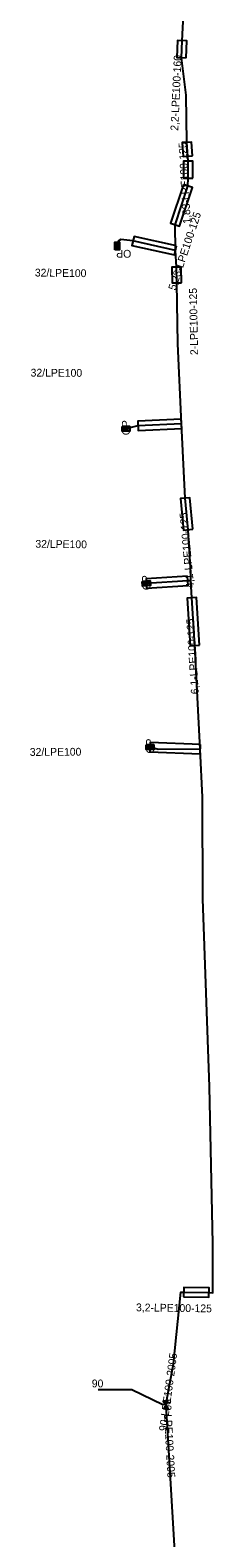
# Model space of a CAD drawing. Extents: x -762921 to -762499, y -1152946 to -1152170.
# Drawn here: x -762777.9 to -762754.4, y -1152560 to -1152366.3 of the extents above; entities that cross this region are included whole.
import ezdxf

# ---------------------------------------------------------------- set-up
doc = ezdxf.new("R2010")
doc.units = 0
for name, color, linetype in [('Vrstva 21', 7, 'Continuous'), ('Vrstva 22', 7, 'Continuous'), ('Vrstva 29', 7, 'Continuous'), ('Vrstva 31', 7, 'Continuous'), ('Vrstva 32', 7, 'Continuous')]:
    doc.layers.add(name, color=color, linetype=linetype)

msp = doc.modelspace()

# ---------------------------------------------------------------- linework, layer by layer
at = {"layer": 'Vrstva 21'}
for points in [[(-762760.45, -1152542.92), (-762759.48, -1152537.62), (-762758.55, -1152528.42), (-762758.16, -1152528.42), (-762754.92, -1152528.47), (-762754.43, -1152528.5), (-762754.43, -1152522.18), (-762754.86, -1152502.03), (-762755.69, -1152477.87), (-762755.75, -1152464.8), (-762756.04, -1152458.65), (-762756.74, -1152445.33), (-762757.13, -1152439.2), (-762757.27, -1152437), (-762757.25, -1152435.97), (-762757.61, -1152430.45), (-762757.98, -1152426.4), (-762758.45, -1152416.83), (-762758.91, -1152406.58), (-762759.05, -1152398.74), (-762759.09, -1152396.71), (-762759.23, -1152394.56), (-762759.27, -1152391.26), (-762757.62, -1152386.29), (-762757.61, -1152385.28), (-762757.61, -1152383.09), (-762757.65, -1152382.46), (-762757.75, -1152380.67), (-762757.84, -1152374.62), (-762758.45, -1152369.81), (-762758.35, -1152367.62), (-762758.14, -1152363.48)], [(-762760.45, -1152542.92), (-762757.89, -1152586.28)]]:
    msp.add_lwpolyline(points, dxfattribs=at)
at = {"layer": 'Vrstva 22'}
for points in [[(-762769.15, -1152540.9), (-762764.8, -1152540.9), (-762760.85, -1152542.85)], [(-762760.72, -1152543.437), (-762760.18, -1152542.404), (-762760.779, -1152542.439), (-762760.121, -1152543.402), (-762760.72, -1152543.437)]]:
    msp.add_lwpolyline(points, dxfattribs=at)
at = {"layer": 'Vrstva 29'}
for points in [[(-762757.85, -1152369.84), (-762757.75, -1152367.65), (-762758.95, -1152367.59), (-762759.05, -1152369.78)], [(-762757.05, -1152382.43), (-762757.15, -1152380.64), (-762758.35, -1152380.7), (-762758.25, -1152382.49)], [(-762757.01, -1152385.28), (-762757.01, -1152383.09), (-762758.21, -1152383.09), (-762758.21, -1152385.28)], [(-762758.19, -1152386.1), (-762759.84, -1152391.07), (-762758.7, -1152391.45), (-762757.05, -1152386.48)], [(-762759.1, -1152393.97), (-762764.54, -1152392.76), (-762764.8, -1152393.94), (-762759.36, -1152395.15)], [(-762758.45, -1152398.73), (-762758.49, -1152396.7), (-762759.69, -1152396.72), (-762759.65, -1152398.75)], [(-762758.48, -1152416.23), (-762764.07, -1152416.51), (-762764.01, -1152417.71), (-762758.42, -1152417.43)], [(-762757.01, -1152430.4), (-762757.38, -1152426.35), (-762758.58, -1152426.45), (-762758.21, -1152430.5)], [(-762757.66, -1152436.4), (-762763, -1152436.75), (-762762.92, -1152437.95), (-762757.58, -1152437.6)], [(-762756.14, -1152445.29), (-762756.53, -1152439.16), (-762757.73, -1152439.24), (-762757.34, -1152445.37)], [(-762756.02, -1152458.05), (-762762.46, -1152457.79), (-762762.5, -1152458.99), (-762756.06, -1152459.25)], [(-762758.17, -1152529.02), (-762754.93, -1152529.07), (-762754.91, -1152527.87), (-762758.15, -1152527.82)]]:
    msp.add_lwpolyline(points, close=True, dxfattribs=at)
at = {"layer": 'Vrstva 31'}
for points in [[(-762759.23, -1152394.56), (-762764.67, -1152393.35), (-762766.25, -1152393.18), (-762766.58, -1152393.39), (-762766.69, -1152394)], [(-762758.45, -1152416.83), (-762764.04, -1152417.11), (-762765.57, -1152417.48)], [(-762757.27, -1152437), (-762757.62, -1152437), (-762762.96, -1152437.35)], [(-762756.04, -1152458.65), (-762761.46, -1152458.68), (-762762.48, -1152458.39)]]:
    msp.add_lwpolyline(points, dxfattribs=at)
at = {"layer": 'Vrstva 32'}
for p, q in [((-762766.516, -1152394.2), (-762766.866, -1152394.198)), ((-762766.514, -1152393.801), (-762766.864, -1152393.799)), ((-762766.702, -1152394.4), (-762766.701, -1152394.199)), ((-762766.867, -1152394.399), (-762766.517, -1152394.401)), ((-762765.975, -1152417.315), (-762765.966, -1152417.665)), ((-762765.97, -1152417.48), (-762765.769, -1152417.475)), ((-762765.765, -1152417.66), (-762765.774, -1152417.31)), ((-762765.366, -1152417.65), (-762765.375, -1152417.3)), ((-762763.37, -1152437.202), (-762763.347, -1152437.551)), ((-762763.359, -1152437.367), (-762763.159, -1152437.353)), ((-762763.147, -1152437.538), (-762763.17, -1152437.189)), ((-762762.749, -1152437.512), (-762762.772, -1152437.163)), ((-762762.884, -1152458.224), (-762762.876, -1152458.574)), ((-762762.88, -1152458.389), (-762762.679, -1152458.384)), ((-762762.675, -1152458.569), (-762762.683, -1152458.219)), ((-762762.276, -1152458.56), (-762762.284, -1152458.21))]:
    msp.add_line(p, q, dxfattribs=at)
for points in [[(-762766.993, -1152394.498), (-762766.987, -1152393.498), (-762766.387, -1152393.502), (-762766.393, -1152394.502), (-762766.993, -1152394.498)], [(-762766.865, -1152394.099), (-762766.614, -1152394.101), (-762766.565, -1152394.087), (-762766.532, -1152394.056), (-762766.515, -1152394.014), (-762766.515, -1152393.985), (-762766.531, -1152393.943), (-762766.564, -1152393.914), (-762766.613, -1152393.9), (-762766.864, -1152393.898)], [(-762766.864, -1152393.799), (-762766.863, -1152393.669), (-762766.845, -1152393.627), (-762766.829, -1152393.612), (-762766.796, -1152393.598), (-762766.746, -1152393.599), (-762766.713, -1152393.613), (-762766.697, -1152393.628), (-762766.681, -1152393.67), (-762766.682, -1152393.8)], [(-762766.078, -1152417.193), (-762765.078, -1152417.167), (-762765.063, -1152417.767), (-762766.062, -1152417.792), (-762766.078, -1152417.193)], [(-762765.675, -1152417.307), (-762765.668, -1152417.558), (-762765.653, -1152417.607), (-762765.621, -1152417.639), (-762765.579, -1152417.655), (-762765.55, -1152417.654), (-762765.508, -1152417.636), (-762765.48, -1152417.602), (-762765.467, -1152417.553), (-762765.474, -1152417.302)], [(-762765.375, -1152417.3), (-762765.245, -1152417.296), (-762765.202, -1152417.312), (-762765.187, -1152417.328), (-762765.172, -1152417.36), (-762765.171, -1152417.41), (-762765.184, -1152417.444), (-762765.199, -1152417.46), (-762765.24, -1152417.478), (-762765.37, -1152417.482)], [(-762763.478, -1152437.084), (-762762.48, -1152437.018), (-762762.441, -1152437.617), (-762763.439, -1152437.682), (-762763.478, -1152437.084)], [(-762763.071, -1152437.182), (-762763.055, -1152437.433), (-762763.037, -1152437.481), (-762763.004, -1152437.512), (-762762.961, -1152437.526), (-762762.932, -1152437.524), (-762762.891, -1152437.504), (-762762.865, -1152437.469), (-762762.854, -1152437.42), (-762762.87, -1152437.169)], [(-762762.772, -1152437.163), (-762762.642, -1152437.154), (-762762.599, -1152437.168), (-762762.583, -1152437.183), (-762762.567, -1152437.215), (-762762.563, -1152437.265), (-762762.575, -1152437.299), (-762762.589, -1152437.316), (-762762.63, -1152437.336), (-762762.76, -1152437.344)], [(-762762.987, -1152458.101), (-762761.987, -1152458.078), (-762761.973, -1152458.678), (-762762.973, -1152458.701), (-762762.987, -1152458.101)], [(-762762.584, -1152458.217), (-762762.578, -1152458.468), (-762762.563, -1152458.516), (-762762.531, -1152458.549), (-762762.489, -1152458.565), (-762762.46, -1152458.564), (-762762.418, -1152458.546), (-762762.39, -1152458.512), (-762762.377, -1152458.463), (-762762.383, -1152458.212)], [(-762762.284, -1152458.21), (-762762.154, -1152458.207), (-762762.112, -1152458.223), (-762762.096, -1152458.239), (-762762.082, -1152458.271), (-762762.08, -1152458.321), (-762762.094, -1152458.355), (-762762.108, -1152458.371), (-762762.15, -1152458.389), (-762762.28, -1152458.392)]]:
    msp.add_lwpolyline(points, dxfattribs=at)

# ---------------------------------------------------------------- texts
at = {"layer": 'Vrstva 21'}
for rotation, p in [(82.19092, (-762760.36, -1152546.32)), (273.1736, (-762760.8, -1152542.19))]:
    msp.add_text('90-LPE100-2005', height=1, rotation=rotation, dxfattribs=at).set_placement(p)
at = {"layer": 'Vrstva 22'}
msp.add_text('90', height=1, rotation=0.05253, dxfattribs=at).set_placement((-762769.96, -1152540.64))
at = {"layer": 'Vrstva 29'}
for s, rotation, p in [('2,2-LPE100-160', 87.38557, (-762758.87, -1152379.21)), ('1,83-LPE100-125', 93.19756, (-762757.25, -1152391.11)), ('5,23-LPE100-125', 71.53701, (-762759.23, -1152399.78)), ('2-LPE100-125', 91.12884, (-762756.31, -1152408)), ('4,1-LPE100-125', 95.21994, (-762756.82, -1152437.91)), ('6,1-LPE100-125', 93.64034, (-762756.22, -1152451.55)), ('3,2-LPE100-125', 359.11588, (-762764.29, -1152530.86))]:
    msp.add_text(s, height=1, rotation=rotation, dxfattribs=at).set_placement(p)
at = {"layer": 'Vrstva 31'}
for rotation, p in [(359.2297, (-762777.27, -1152397.91)), (359.2297, (-762777.27, -1152397.91)), (359.71662, (-762777.81, -1152410.77)), (359.71662, (-762777.81, -1152410.77)), (359.33024, (-762777.2, -1152432.76)), (359.33024, (-762777.2, -1152432.76)), (0.31713, (-762777.91, -1152459.51)), (0.31713, (-762777.91, -1152459.51))]:
    msp.add_text('32/LPE100', height=1, rotation=rotation, dxfattribs=at).set_placement(p)
at = {"layer": 'Vrstva 32'}
for rotation, p in [(179.62746, (-762764.89, -1152394.5)), (179.62746, (-762764.89, -1152394.5)), (91.4666, (-762765.05, -1152418.29)), (91.4666, (-762765.05, -1152418.29)), (93.74998, (-762762.41, -1152438.18)), (93.74998, (-762762.41, -1152438.18)), (91.32156, (-762761.96, -1152459.2)), (91.32156, (-762761.96, -1152459.2))]:
    msp.add_text('OP', height=1, rotation=rotation, dxfattribs=at).set_placement(p)

doc.saveas('drawing.dxf')
